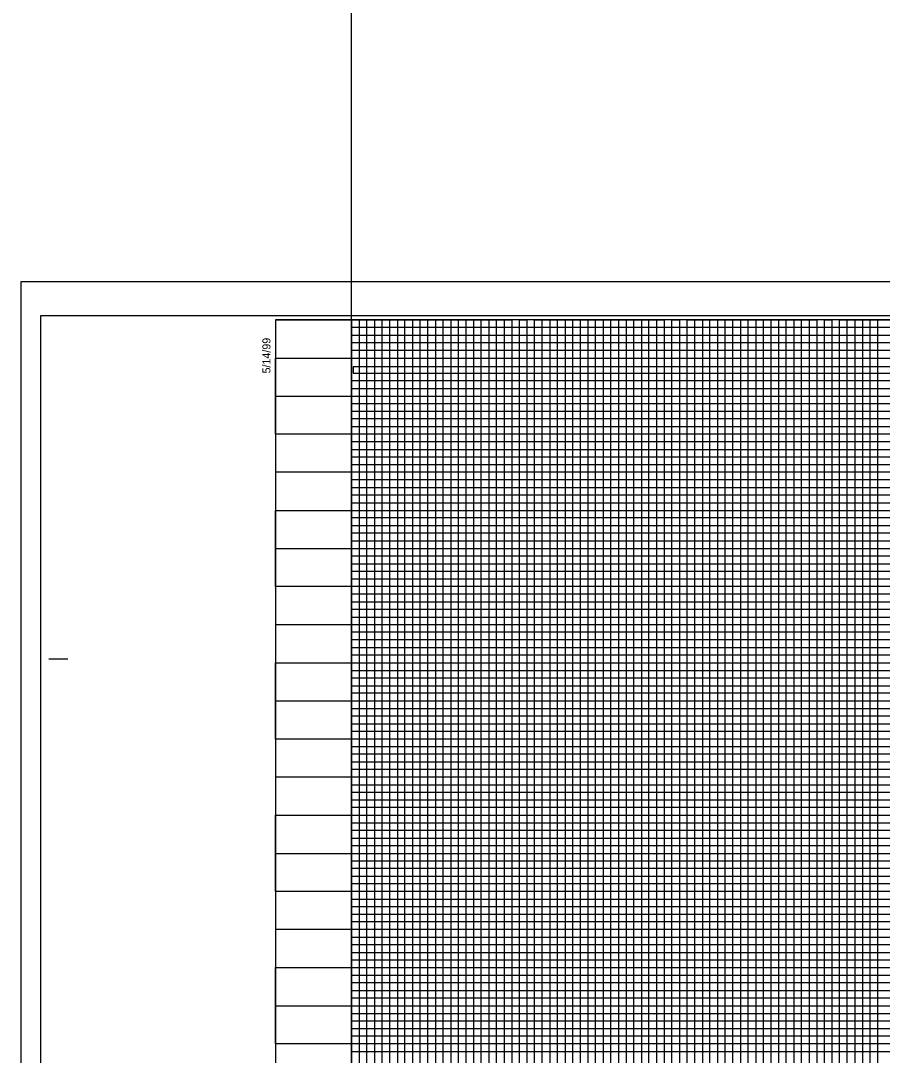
# Model space of a CAD drawing. Extents: x 2345490 to 2436403, y 465165 to 573888.
# Drawn here: x 2381550 to 2382115, y 495635 to 496314 of the extents above; entities that cross this region are included whole.
import ezdxf

# ---------------------------------------------------------------- set-up
doc = ezdxf.new("R2010")
doc.units = 0
for name, color, linetype in [('Old_Level_18', 7, 'Continuous'), ('Old_Level_41', 7, 'Continuous'), ('Old_Level_42', 7, 'Continuous'), ('Old_Level_43', 7, 'Continuous'), ('Old_Level_50', 7, 'Continuous'), ('Old_Level_51', 7, 'Continuous'), ('Old_Level_63', 7, 'Continuous')]:
    doc.layers.add(name, color=color, linetype=linetype)

msp = doc.modelspace()

# ---------------------------------------------------------------- linework, layer by layer
at = {"layer": 'Old_Level_18'}
msp.add_lwpolyline([(2383216.79875, 496117.6345), (2381716.79875, 496117.6345), (2381716.79875, 495067.6345), (2383216.79875, 495067.6345)], close=True, dxfattribs=at)
at = {"layer": 'Old_Level_41'}
msp.add_line((2381568.29875, 495895.1345), (2381580.79875, 495895.1345), dxfattribs=at)
for points in [[(2381716.79875, 496117.6345), (2381766.79875, 496117.6345), (2381766.79875, 495092.6345), (2381816.79875, 495092.6345), (2381816.79875, 496117.6345), (2381866.79875, 496117.6345), (2381866.79875, 495092.6345), (2381916.79875, 495092.6345), (2381916.79875, 496117.6345), (2381966.79875, 496117.6345), (2381966.79875, 495092.6345), (2382016.79875, 495092.6345), (2382016.79875, 496117.6345), (2382066.79875, 496117.6345), (2382066.79875, 495092.6345), (2382116.79875, 495092.6345)], [(2381791.79875, 495092.6345), (2381791.79875, 496117.6345), (2381841.79875, 496117.6345), (2381841.79875, 495092.6345), (2381891.79875, 495092.6345), (2381891.79875, 496117.6345), (2381941.79875, 496117.6345), (2381941.79875, 495092.6345), (2381991.79875, 495092.6345), (2381991.79875, 496117.6345), (2382041.79875, 496117.6345), (2382041.79875, 495092.6345), (2382091.79875, 495092.6345), (2382091.79875, 496117.6345), (2382141.79875, 496117.6345)], [(2381716.79875, 496067.6345), (2383016.74875, 496067.6345)], [(2383016.74875, 496017.6345), (2381716.79875, 496017.6345), (2381716.79875, 495967.5845), (2383216.79875, 495967.5845)], [(2383216.79875, 495942.6345), (2381716.79875, 495942.6345), (2381716.79875, 495992.6345), (2383016.74875, 495992.6345)], [(2383216.79875, 495917.6345), (2381716.79875, 495917.6345), (2381716.79875, 495867.6345), (2383216.79875, 495867.6345)], [(2383216.79875, 495842.6345), (2381716.79875, 495842.6345), (2381716.79875, 495892.6345), (2383216.79875, 495892.6345)], [(2383216.79875, 495817.6345), (2381716.79875, 495817.6345), (2381716.79875, 495767.6345), (2383216.79875, 495767.6345)], [(2383216.79875, 495717.6345), (2381716.79875, 495717.6345), (2381716.79875, 495667.6345), (2383216.79875, 495667.6345)]]:
    msp.add_lwpolyline(points, dxfattribs=at)
at = {"layer": 'Old_Level_42'}
for points in [[(2383016.74875, 496042.6345), (2381716.89875, 496042.6345), (2381716.89875, 496092.5845), (2383016.74875, 496092.5845)], [(2383216.79875, 495742.6345), (2381716.79875, 495742.6345), (2381716.79875, 495792.6345), (2383216.79875, 495792.6345)], [(2383216.79875, 495642.6345), (2381716.79875, 495642.6345), (2381716.79875, 495692.6345), (2383216.79875, 495692.6345)]]:
    msp.add_lwpolyline(points, dxfattribs=at)
at = {"layer": 'Old_Level_43'}
for p, q in [((2383166.79875, 495937.6345), (2381766.79875, 495937.6345)), ((2381766.79875, 495937.6345), (2381766.79875, 495932.6345)), ((2381766.79875, 495932.6345), (2383166.79875, 495932.6345)), ((2383166.79875, 495912.6345), (2381766.79875, 495912.6345))]:
    msp.add_line(p, q, dxfattribs=at)
for points in [[(2381771.79875, 496117.6345), (2381776.79875, 496117.6345), (2381781.79875, 496117.6345), (2381786.79875, 496117.6345), (2381796.79875, 496117.6345), (2381763.74875, 496117.6345), (2381768.74875, 496117.6345), (2381726.79875, 496117.6345), (2381731.79875, 496117.6345), (2381736.79875, 496117.6345), (2381746.79875, 496117.6345), (2381751.79875, 496117.6345), (2381756.79875, 496117.6345), (2381761.79875, 496117.6345), (2381771.79875, 496117.6345), (2381771.79875, 495092.6345)], [(2381776.79875, 495092.6345), (2381776.79875, 496117.6345), (2381781.79875, 496117.6345), (2381781.79875, 495092.6345)], [(2381786.79875, 495092.6345), (2381786.79875, 496117.6345), (2381796.79875, 496117.6345), (2381796.79875, 495092.6345)], [(2381801.79875, 495092.6345), (2381801.79875, 496117.6345), (2381806.79875, 496117.6345), (2381806.79875, 495092.6345)], [(2381811.79875, 495092.6345), (2381811.79875, 496117.6345), (2381821.79875, 496117.6345), (2381821.79875, 495092.6345)], [(2381826.79875, 495092.6345), (2381826.79875, 496117.6345), (2381831.79875, 496117.6345), (2381831.79875, 495092.6345)], [(2381836.79875, 495092.6345), (2381836.79875, 496117.6345), (2381846.79875, 496117.6345), (2381846.79875, 495092.6345)], [(2381851.79875, 495092.6345), (2381851.79875, 496117.6345), (2381856.79875, 496117.6345), (2381856.79875, 495092.6345)], [(2381861.79875, 495092.6345), (2381861.79875, 496117.6345), (2381871.79875, 496117.6345), (2381871.79875, 495092.6345)], [(2381876.79875, 495092.6345), (2381876.79875, 496117.6345), (2381881.79875, 496117.6345), (2381881.79875, 495092.6345)], [(2381886.79875, 495092.6345), (2381886.79875, 496117.6345), (2381896.79875, 496117.6345), (2381896.79875, 495092.6345)], [(2381901.79875, 495092.6345), (2381901.79875, 496117.6345), (2381906.79875, 496117.6345), (2381906.79875, 495092.6345)], [(2381911.79875, 495092.6345), (2381911.79875, 496117.6345), (2381921.79875, 496117.6345), (2381921.79875, 495092.6345)], [(2381926.79875, 495092.6345), (2381926.79875, 496117.6345), (2381931.79875, 496117.6345), (2381931.79875, 495092.6345)], [(2381936.79875, 495092.6345), (2381936.79875, 496117.6345), (2381946.79875, 496117.6345), (2381946.79875, 495092.6345)], [(2381951.79875, 495092.6345), (2381951.79875, 496117.6345), (2381956.79875, 496117.6345), (2381956.79875, 495092.6345)], [(2381961.79875, 495092.6345), (2381961.79875, 496117.6345), (2381971.79875, 496117.6345), (2381971.79875, 495092.6345)], [(2381976.79875, 495092.6345), (2381976.79875, 496117.6345), (2381976.79875, 496117.6345), (2381981.79875, 496117.6345), (2381981.79875, 495092.6345)], [(2381986.79875, 495092.6345), (2381986.79875, 496117.6345), (2381996.79875, 496117.6345), (2381996.79875, 495092.6345)], [(2382001.79875, 495092.6345), (2382001.79875, 496117.6345), (2382006.79875, 496117.6345), (2382006.79875, 495092.6345)], [(2382011.79875, 495092.6345), (2382011.79875, 496117.6345), (2382021.79875, 496117.6345), (2382021.79875, 495092.6345)], [(2382026.79875, 495092.6345), (2382026.79875, 496117.6345), (2382031.79875, 496117.6345), (2382031.79875, 495092.6345)], [(2382036.79875, 495092.6345), (2382036.79875, 496117.6345), (2382046.79875, 496117.6345), (2382046.79875, 495092.6345)], [(2382051.79875, 495092.6345), (2382051.79875, 496117.6345), (2382056.79875, 496117.6345), (2382056.79875, 495092.6345)], [(2382061.79875, 495092.6345), (2382061.79875, 496117.6345), (2382071.79875, 496117.6345), (2382071.79875, 495092.6345)], [(2382076.79875, 495092.6345), (2382076.79875, 496117.6345), (2382081.79875, 496117.6345), (2382081.79875, 495092.6345)], [(2382086.79875, 495092.6345), (2382086.79875, 496117.6345), (2382096.79875, 496117.6345), (2382096.79875, 495092.6345)], [(2382101.79875, 496117.6345), (2382101.79875, 495092.6345), (2382106.79875, 495092.6345), (2382106.79875, 496117.6345)], [(2382101.79875, 496117.0345), (2382101.79875, 495092.6345), (2382106.79875, 495092.6345), (2382106.79875, 496117.0345)], [(2382111.79875, 495092.6345), (2382111.79875, 496117.6345), (2382121.79875, 496117.6345)], [(2383016.74875, 496112.6345), (2381766.79875, 496112.6345), (2381766.79875, 496107.6345), (2383016.74875, 496107.6345)], [(2383016.74875, 496102.6345), (2381766.79875, 496102.6345), (2381766.79875, 496097.6345), (2383016.74875, 496097.6345)], [(2383016.74875, 496086.8845), (2381767.79875, 496086.8845), (2381767.79875, 496082.6345), (2383016.74875, 496082.6345)], [(2383016.74875, 496077.6345), (2381766.79875, 496077.6345), (2381766.79875, 496072.6345), (2383016.74875, 496072.6345)], [(2383016.74875, 496062.6345), (2381766.79875, 496062.6345), (2381766.79875, 496057.6345), (2383016.74875, 496057.6345)], [(2383016.74875, 496052.6345), (2381766.79875, 496052.6345), (2381766.79875, 496047.6345), (2383016.74875, 496047.6345)], [(2383016.74875, 496037.6345), (2381766.79875, 496037.6345), (2381766.79875, 496032.6345), (2383016.74875, 496032.6345)], [(2383016.74875, 496027.6345), (2381766.79875, 496027.6345), (2381766.79875, 496022.6345), (2383016.74875, 496022.6345)], [(2383016.74875, 496012.6345), (2381766.79875, 496012.6345), (2381766.79875, 496007.6345), (2383016.74875, 496007.6345)], [(2383016.74875, 496002.6345), (2381766.79875, 496002.6345), (2381766.79875, 495997.6345), (2383016.74875, 495997.6345)], [(2383016.74875, 495987.6345), (2381766.79875, 495987.6345), (2381766.79875, 495982.6345), (2383016.74875, 495982.6345)], [(2383166.79875, 495977.6345), (2381766.79875, 495977.6345), (2381766.79875, 495977.6345), (2381766.79875, 495957.6345), (2383166.79875, 495957.6345)], [(2381766.79875, 495972.6345), (2383166.79875, 495972.6345)], [(2383166.79875, 495962.6345), (2381766.79875, 495962.6345)], [(2383166.79875, 495952.6345), (2381766.79875, 495952.6345), (2381766.79875, 495947.6345), (2383166.79875, 495947.6345)], [(2383166.79875, 495927.6345), (2381766.79875, 495927.6345), (2381766.79875, 495922.6345), (2383166.79875, 495922.6345)], [(2383166.79875, 495907.6345), (2381766.79875, 495907.6345), (2381766.79875, 495902.6345), (2383166.79875, 495902.6345)], [(2383166.79875, 495897.6345), (2381766.79875, 495897.6345)], [(2381766.79875, 495887.6345), (2383166.79875, 495887.6345)], [(2383166.79875, 495882.6345), (2381766.79875, 495882.6345), (2381766.79875, 495877.6345), (2383166.79875, 495877.6345)], [(2383166.79875, 495872.6345), (2381766.79875, 495872.6345), (2381766.79875, 495862.6345), (2383166.79875, 495862.6345)], [(2383166.79875, 495857.6345), (2381766.79875, 495857.6345), (2381766.79875, 495852.6345), (2383166.79875, 495852.6345)], [(2383166.79875, 495847.6345), (2381766.79875, 495847.6345), (2381766.79875, 495837.6345), (2383166.79875, 495837.6345)], [(2383166.79875, 495832.6345), (2381766.79875, 495832.6345), (2381766.79875, 495827.6345), (2383166.79875, 495827.6345)], [(2383166.79875, 495822.6345), (2381766.79875, 495822.6345), (2381766.79875, 495812.6345), (2383166.79875, 495812.6345)], [(2383166.79875, 495807.6345), (2381766.79875, 495807.6345), (2381766.79875, 495802.6345), (2383166.79875, 495802.6345)], [(2383166.79875, 495797.6345), (2381766.79875, 495797.6345), (2381766.79875, 495787.6345), (2383166.79875, 495787.6345)], [(2383166.79875, 495782.6345), (2381766.79875, 495782.6345), (2381766.79875, 495777.6345), (2383166.79875, 495777.6345)], [(2383166.79875, 495772.6345), (2381766.79875, 495772.6345), (2381766.79875, 495762.6345), (2383166.79875, 495762.6345)], [(2383166.79875, 495757.6345), (2381766.79875, 495757.6345), (2381766.79875, 495752.6345), (2383166.79875, 495752.6345)], [(2383166.79875, 495747.6345), (2381766.79875, 495747.6345), (2381766.79875, 495737.6345), (2383166.79875, 495737.6345)], [(2383166.79875, 495732.6345), (2381766.79875, 495732.6345), (2381766.79875, 495727.6345), (2383166.79875, 495727.6345)], [(2383166.79875, 495722.6345), (2381766.79875, 495722.6345), (2381766.79875, 495712.6345), (2383166.79875, 495712.6345)], [(2383166.79875, 495707.6345), (2381766.79875, 495707.6345), (2381766.79875, 495702.6345), (2383166.79875, 495702.6345)], [(2383166.79875, 495697.6345), (2381766.79875, 495697.6345), (2381766.79875, 495687.6345), (2383166.79875, 495687.6345)], [(2383166.79875, 495682.6345), (2381766.79875, 495682.6345), (2381766.79875, 495677.6345), (2383166.79875, 495677.6345)], [(2383166.79875, 495672.6345), (2381766.79875, 495672.6345), (2381766.79875, 495662.6345), (2383166.79875, 495662.6345)], [(2383166.79875, 495657.6345), (2381766.79875, 495657.6345), (2381766.79875, 495652.6345), (2383166.79875, 495652.6345)], [(2383166.79875, 495647.6345), (2381766.79875, 495647.6345), (2381766.79875, 495637.6345), (2383166.79875, 495637.6345)]]:
    msp.add_lwpolyline(points, dxfattribs=at)
at = {"layer": 'Old_Level_50'}
msp.add_lwpolyline([(2383229.29875, 496120.1845), (2381562.79875, 496120.1845), (2381562.79875, 495065.0845), (2383229.29875, 495065.0845)], close=True, dxfattribs=at)
at = {"layer": 'Old_Level_51'}
msp.add_lwpolyline([(2383233.79875, 496142.6345), (2381549.79875, 496142.6345), (2381549.79875, 495042.6345), (2383233.79875, 495042.6345)], close=True, dxfattribs=at)
at = {"layer": 'Old_Level_63'}
msp.add_line((2381766.79875, 495092.6345), (2381766.79875, 497592.6345), dxfattribs=at)

# ---------------------------------------------------------------- texts
at = {"layer": 'Old_Level_41'}
msp.add_text('5/14/99', height=5.25, rotation=90, dxfattribs=at).set_placement((2381713.54875, 496082.4345))

doc.saveas('drawing.dxf')
